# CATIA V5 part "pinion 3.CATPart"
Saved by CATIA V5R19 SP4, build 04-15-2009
Part number: pinion 3
Bounding box of the stored display mesh (mm): x 0 to 22.15, y -25.002 to 25.002, z -24.82 to 24.82
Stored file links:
  G:\EU_thinkMotion\CFAO_2010\MMS_groupe1\MMS_groupe1\A reprendre\OK\rdeneffle\pinion 3.CATPart
  G:\EU_thinkMotion\CFAO_2010\MMS_groupe1\MMS_groupe1\A reprendre\OK\rdeneffle\pinion 2.CATPart
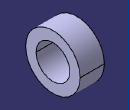
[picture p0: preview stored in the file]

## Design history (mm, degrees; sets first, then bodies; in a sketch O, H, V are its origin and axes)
Parameters
  `rayon interieur` = 15.505 mm
  `rayon extérieur` = 25.002 mm
Body1 (main body)
Body2
  Sketch1 on yz-plane, origin (0, 0, 0), H (0, 1, 0), V (0, 0, 1)
    circle A1 centre (0, 0) radius 15.505
    circle A2 centre (0, 0) radius 25.002
    radius A2 = 25.002 {= `rayon extérieur`}
    radius A1 = 15.505 {= `rayon interieur`}
  Pad1: profile Sketch1, direction (1, 0, 0), length 22.15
